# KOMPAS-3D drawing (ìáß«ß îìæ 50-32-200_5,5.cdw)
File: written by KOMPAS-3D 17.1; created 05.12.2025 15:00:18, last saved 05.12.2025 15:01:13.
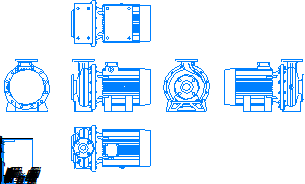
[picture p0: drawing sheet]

Sheet 1: A4, portrait

Title block, sheet 1: name: Насос МНС / 50-32-200_5,5; material: Сталь 10  ГОСТ 1050-88; mass: 156,7; sheets: 1; sheet format: A4

Views: Вид 1, Спереди, Проекционный вид 2, Проекционный вид 4, Проекционный вид 5, Проекционный вид 6
Referenced files in \\adlc.lan\data\АДЛ_ПКД\3D-модели\ADL production\Насосы ГРАНПАМП\Насосы ГРАНПАМП серии МНС\KOMPAS 3D\: Насос МНС 50-32-200_5,5.m3d
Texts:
  Andrey
  АДЛ
Dimensions and other numbers on the sheet: 1:1; 1; 50-32-200_5,5; 156,7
